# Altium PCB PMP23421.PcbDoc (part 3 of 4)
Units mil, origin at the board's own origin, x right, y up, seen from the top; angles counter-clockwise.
Board outline 2755.91 x 7559.06 mil, 8 copper layers (Top Layer, Signal Layer 1, Signal Layer 2, Signal Layer 3, Signal Layer 4, Signal Layer 5, Signal Layer 6, Bottom Layer), stack 60.4 mil thick; 211 components, 135 nets, 708 pads, 652 vias.
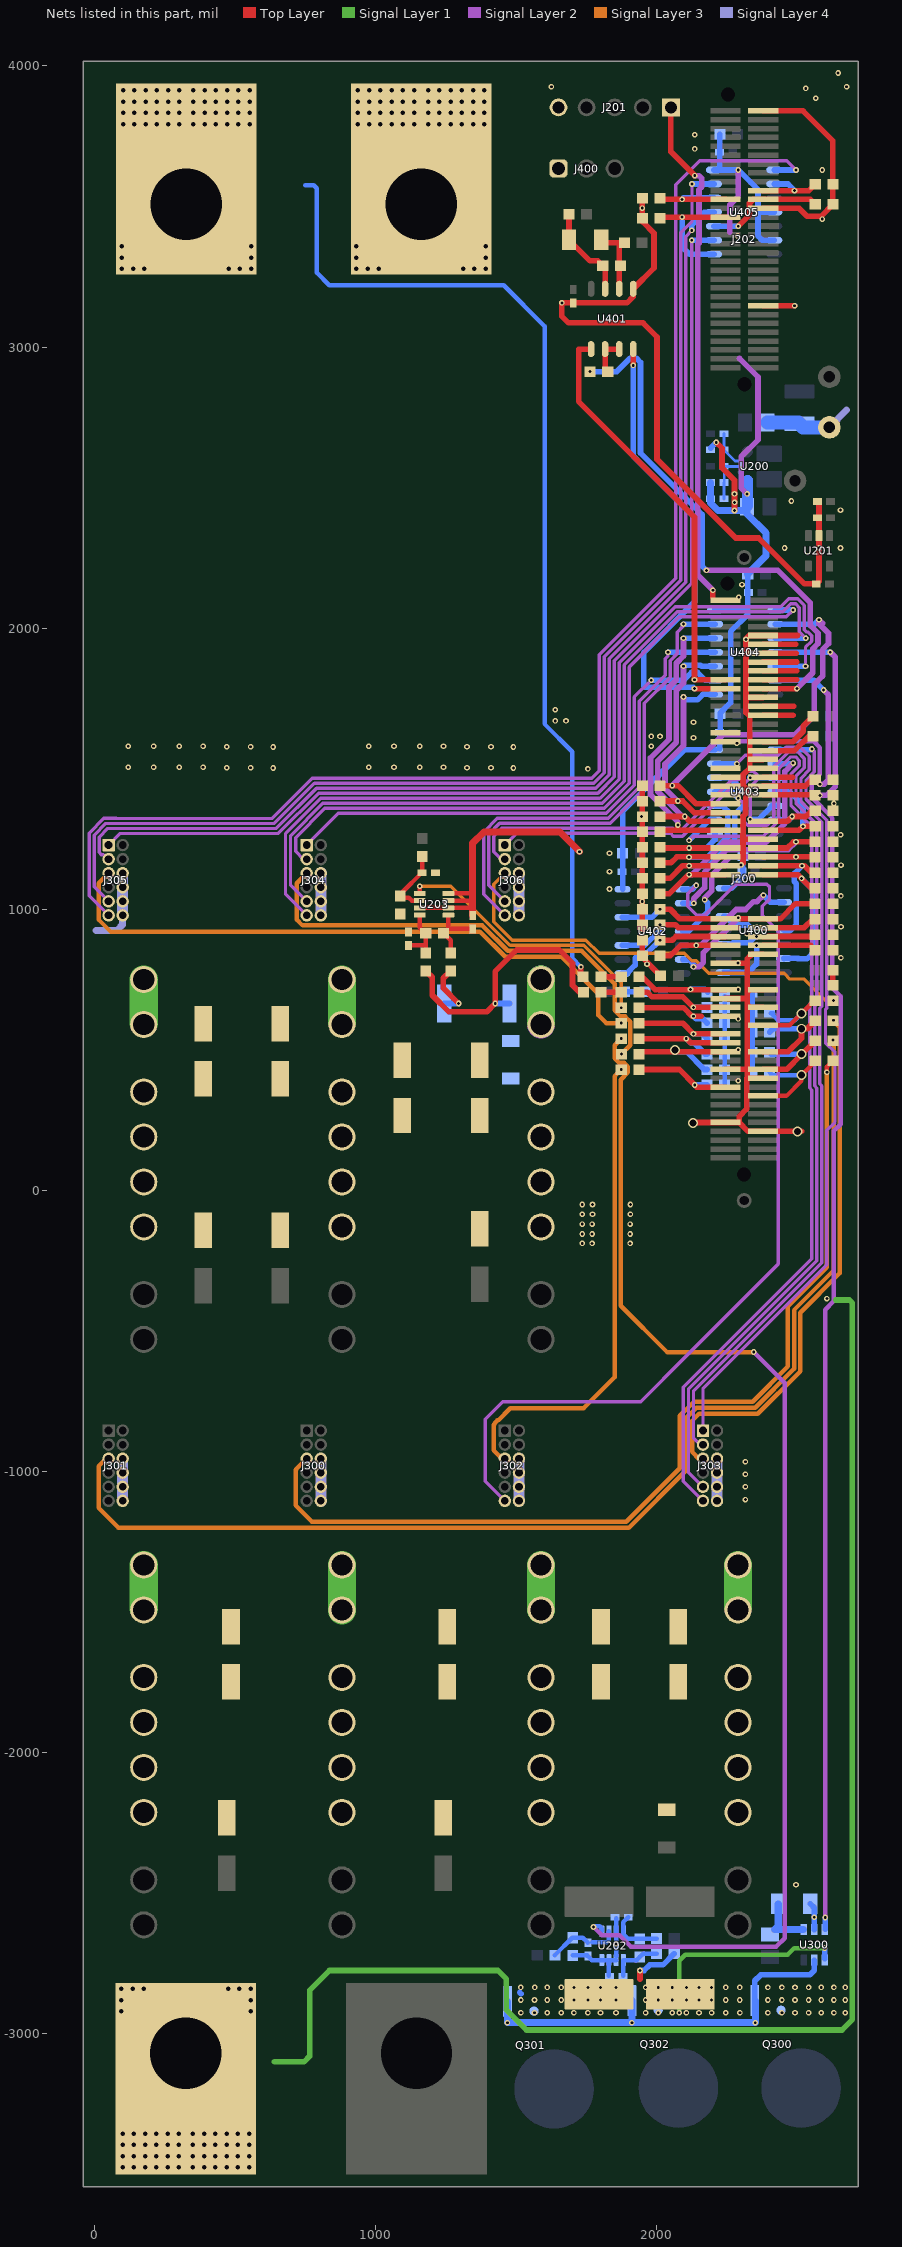
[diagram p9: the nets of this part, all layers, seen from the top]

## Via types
v1: diameter 20, hole 10, Top Layer to Bottom Layer, 398 vias
v2: diameter 32, hole 16, Top Layer to Bottom Layer, 232 vias
v3: diameter 19.68, hole 7.87, Top Layer to Bottom Layer, 12 vias
v4: diameter 35, hole 25, Top Layer to Bottom Layer, 7 vias
v5: diameter 20, hole 10, Top Layer to Bottom Layer, tented both sides, 3 vias

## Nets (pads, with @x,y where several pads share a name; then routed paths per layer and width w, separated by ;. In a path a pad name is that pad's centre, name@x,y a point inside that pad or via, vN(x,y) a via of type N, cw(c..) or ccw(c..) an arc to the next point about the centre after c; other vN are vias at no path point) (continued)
BUF_PWM6L_D: J302.11 U402.8 | length 3460.8
  Signal Layer 2 w12: J302.11@1459.45,-1104.33 1390,-1034.88 1390,-813.81 1452.21,-751.6 1942.37,-751.6 2022.94,-671.03 2022.94,-670.85 2431.97,-261.82 2431.97,921.53 2375.4,978.11 2375.4,1010.91 2400.88,1036.39 2400.88,1079.97 2391.57,1089.29 2281.12,1089.29 2170.03,978.2 2141.8,978.2 2109.61,1010.39 2109.61,1054.61 v1(2140,1085)
  Bottom Layer w20: U402.8@2092.28,1071.41 2126.41,1071.41 v1(2140,1085)
BUF_PWM7H_D: J303.1 U403.8 | length 2811.7
  Signal Layer 2 w12: J303.1@2164.17,-854.33 2164.17,-705.83 2605,-265 2605,214.2 2634,243.2 2634,491 2600,525 2600,643.28 ; v1(2551.8,1570) 2560.2,1561.6 2560.2,1488.85 2530.84,1459.49 2530.84,1390.51 2605,1316.35 2605,648.28 2600.54,643.83
  Bottom Layer w20: U403.8@2421.7,1567.72 2549.52,1567.72 v1(2551.8,1570)
BUF_PWM7L_D: J303.3 U403.6 | length 3079.9
  Signal Layer 2 w12: J303.3@2164.17,-904.33 2154.55,-904.33 2130.33,-880.1 2130.33,-714.5 2587.2,-257.63 2587.2,371.55 2579.9,378.85 2579.9,648.36 2587.2,655.66 2587.2,1308.98 2513.04,1383.14 2513.04,1466.86 2542.4,1496.22 2542.4,1543.78 2508.78,1577.4 2461.22,1577.4 2431.54,1547.72 2315,1547.72 v1(2285,1517.72)
  Bottom Layer w20: U403.6@2207.13,1517.72 v1(2285,1517.72)
BUF_PWM8H_D: J303.9 U403.4 | length 3480.8
  Signal Layer 2 w12: J303.9@2164.17,-1054.33 2112.53,-1002.68 2112.53,-707.13 2569.4,-250.25 2569.4,364.18 2562.1,371.48 2562.1,655.73 2569.4,663.03 2569.4,1301.6 2495.24,1375.77 2495.24,1474.23 2524.6,1503.6 2524.6,1536.4 2501.4,1559.6 2468.6,1559.6 2416.04,1507.04 2416.04,1322.04 2392.2,1298.2 2323.25,1298.2 2310.48,1310.97 2310.48,1374.52 v1(2290,1395)
  Bottom Layer w20: U403.4@2207.13,1417.72 2267.28,1417.72 v1(2290,1395)
BUF_PWM8L_D: J303.11 U403.2 | length 3651.2
  Signal Layer 2 w12: v1(2115,1245) 2129.91,1259.91 2379.08,1259.91 2433.84,1314.67 2433.84,1499.67 2475.97,1541.8 2494.03,1541.8 2506.8,1529.03 2506.8,1510.97 2477.44,1481.61 2477.44,1368.39 2551.6,1294.23 2551.6,670.4 2544.3,663.1 2544.3,472.86 2543.97,472.54 2543.97,364.44 2551.6,356.81 2551.6,-242.88 2094.73,-699.75 2094.73,-1034.88 J303.11@2164.17,-1104.33
  Bottom Layer w20: v1(2115,1245) 2187.72,1317.72 U403.2@2207.13,1317.72
BUF_PWM9H_C: J306.1 U403.10 | length 1083.7
  Signal Layer 2 w12: J306.1@1459.45,1228.35 1501.1,1270 2049,1270 2058.6,1260.4 2091.4,1260.4 2273.81,1442.8 2307.37,1442.8 v1(2332.28,1467.72)
  Bottom Layer w20: v1@2330,1470 v1(2332.28,1467.72) U403.10@2421.7,1467.72 U403.10@2432.8,1467.72
BUF_PWM9L_C: J306.3 U403.12 | length 1426.4
  Signal Layer 2 w12: J306.3@1459.45,1178.35 1446.65,1178.35 1420,1205 1420,1260 1447.8,1287.8 2056.37,1287.8 2065.97,1278.2 2084.03,1278.2 2266.43,1460.6 2290.6,1460.6 2320,1490 2345,1490 2355,1480 2355,1458.48 2332.28,1435.77 v1(2332.28,1320)
  Bottom Layer w20: v1(2332.28,1320) 2361.5,1320 2409.21,1367.72 U403.12@2421.7,1367.72
BUF_PWM11H_C: J306.9 U404.6 | length 1640
  Signal Layer 2 w12: J306.9@1459.45,1028.35 1402.2,1085.6 1402.2,1267.37 1440.43,1305.6 1835,1305.6 1955.8,1426.4 1955.8,1732.86 2047.4,1824.46 2047.4,1884.14 2073.2,1909.94 2073.2,1986.22 2095,2008.02 v1(2095,2014.42)
  Bottom Layer w20: v1(2095,2014.42) U404.6@2207.13,2014.42
BUF_PWM11L_C: J306.11 U404.4 | length 1637
  Signal Layer 2 w12: J306.11@1459.45,978.35 1384.4,1053.4 1384.4,1274.75 1433.05,1323.4 1827.63,1323.4 1938,1433.77 1938,1740.24 2029.6,1831.84 2029.6,1891.51 2040,1901.91 v1(2040,1914.42)
  Bottom Layer w20: v1(2040,1914.42) U404.4@2207.13,1914.42
BUF_PWM12H_D: J304.1 U404.2 | length 1903
  Signal Layer 2 w12: J304.1@754.72,1228.35 754.72,1229.73 866.2,1341.2 1820.25,1341.2 1920.2,1441.15 1920.2,1755.2 v1(1980,1815)
  Bottom Layer w20: v1(1980,1815) 2096.22,1815 2123.45,1842.23 2144.83,1842.23 2172.64,1814.42 U404.2@2207.13,1814.42
BUF_PWM12L_D: J304.3 U404.8 | length 2511
  Signal Layer 2 w12: J304.3@754.72,1178.35 742.4,1178.35 715,1205.75 715,1255 819,1359 1812.88,1359 1902.4,1448.52 1902.4,1861.82 2080.53,2039.95 2460.53,2039.95 v1(2485,2064.42)
  Bottom Layer w20: U404.8@2421.7,2064.42 v1(2485,2064.42)
BUF_PWM13H_D: J304.9 U404.10 | length 2883
  Signal Layer 2 w12: J304.9@754.72,1028.35 697.2,1085.87 697.2,1262.37 811.63,1376.8 1805.51,1376.8 1884.6,1455.89 1884.6,1869.19 2073.16,2057.75 2447.5,2057.75 2475.97,2086.22 2494.03,2086.22 2506.8,2073.45 2506.8,1987.62 v1(2530,1964.42)
  Bottom Layer w20: U404.10@2421.7,1964.42 v1(2530,1964.42)
BUF_PWM13L_D: J304.11 U404.12 | length 3112.7
  Signal Layer 2 w12: J304.11@754.72,978.35 679.4,1053.67 679.4,1269.75 804.25,1394.6 1798.13,1394.6 1866.8,1463.27 1866.8,1876.57 2065.79,2075.55 2440.13,2075.55 2468.6,2104.02 2501.4,2104.02 2524.6,2080.82 2524.6,1994.99 2533.37,1986.22 2539.03,1986.22 2551.8,1973.45 2551.8,1954.28 2528.84,1931.32 v1(2528.84,1864.42)
  Bottom Layer w20: U404.12@2421.7,1864.42 v1(2528.84,1864.42)
BUF_PWM15H_D: J305.1 U405.2 | length 4001.7
  Signal Layer 2 w12: J305.1@50,1228.35 91.4,1269.75 654.23,1269.75 796.88,1412.4 1790.76,1412.4 1849,1470.64 1849,1883.94 2124.3,2159.24 v1(2124.3,3380)
  Bottom Layer w20: v1(2124.3,3380) U405.2@2203.28,3380
BUF_PWM15L_D: J305.3 U405.4 | length 4180.4
  Signal Layer 2 w12: J305.3@50,1178.35 47.81,1178.35 31.65,1194.5 24.23,1194.5 16.15,1202.57 16.15,1256.15 47.55,1287.55 646.85,1287.55 789.51,1430.2 1783.39,1430.2 1831.2,1478.01 1831.2,1891.31 2102.5,2162.61 2102.5,3393.03 2124.3,3414.83 v1(2124.3,3415)
  Bottom Layer w20: v1(2124.3,3415) 2124.3,3435 2169.3,3480 U405.4@2203.28,3480
BUF_PWM16H_D: J305.9 U405.6 | length 4465.5
  Signal Layer 2 w12: J305.9@50,1028.35 -1.65,1079.99 -1.65,1263.53 40.17,1305.35 639.48,1305.35 782.13,1448 1776.02,1448 1813.4,1485.38 1813.4,1898.68 2084.7,2169.98 2084.7,3406.23 2125,3446.53 v1(2125,3580)
  Bottom Layer w20: v1(2125,3580) U405.6@2203.28,3580
BUF_PWM16L_D: J305.11 U405.8 | length 4978.9
  Signal Layer 2 w12: J305.11@50,978.35 -19.45,1047.79 -19.45,1270.9 33.15,1323.5 76.79,1323.5 77.14,1323.15 632.11,1323.15 774.76,1465.8 1768.64,1465.8 1795.6,1492.76 1795.6,1906.06 2066.9,2177.36 2066.9,3576.9 2152.09,3662.09 2462.91,3662.09 v1(2495,3630)
  Bottom Layer w20: U405.8@2417.84,3630 v1(2495,3630)
CAN_RX_A: J200.80
CAN_TX_A: J200.82
CS+_total_charge_current_battery: C300.1 C307.1 C308.1 R202.2 R230.2 R300.2 TP333.1 TP345.1 | length 1603.2
  Top Layer w20: R230.2@1178.11,781.04 1201.12,758.02 1201.12,694.13 1260.25,635 1395,635 v1(1425,665) 1425,778.56 1501.44,855 1653.61,855 1700.27,808.35 1700.27,729.87 1725.14,705 R202.2@1738.56,705
  Signal Layer 2 w100: TP333.1@1588.45,590 TP333.1@1588.45,590.2 TP345.1@1588.45,750.2
  Signal Layer 1 w100: TP333.1@1588.45,595 TP345.1@1588.45,750.2
  Signal Layer 3 w100: TP333.1@1588.45,593.65 TP345.1@1588.45,750.2
  Signal Layer 4 w100: TP333.1@1588.45,594.23 TP345.1@1588.45,750.2
  Bottom Layer w20: v1(1425,665) R300.2@1476.14,665
CS-_total_charge_current_battery: C301.1 C302.1 C303.1 C304.1 C305.1 C306.1 R201.2 R232.2 R300.1 T300.1 TP300.1 TP303.1 TP306.1 TP309.1 TP312.1 TP315.1 TP324.1 TP327.1 TP330.1 TP336.1 TP339.1 TP342.1 | length 4971.5
  Top Layer w20: R232.2@1266.69,781.04 1240.49,754.84 1240.49,719.51 v1(1295,665) ; R201.2@1730,763.26 v1(1730,795)
  Signal Layer 1 w100: TP309.1@175,-1487.48 TP300.1@175,-1332.48 ; TP327.1@175,595.2 TP339.1@175,750.2 ; TP312.1@879.72,-1494.72 TP312.1@879.72,-1492.48 TP303.1@879.72,-1332.48 ; TP342.1@879.72,595 TP330.1@879.72,750.2 ; TP315.1@1588.45,-1490 TP306.1@1588.45,-1332.48 ; TP336.1@2289.17,-1486.1 TP324.1@2289.17,-1332.48
  Signal Layer 3 w12: T300.1@161.42,3673.23 T300.1@326.77,3507.87
  Bottom Layer w16: 750,3575 780,3575 790,3565 790,3265 835,3220 1455,3220 1600.66,3074.34 1600.66,1659.34 1699.53,1560.47 1699.53,825.47 v1(1730,795)
  Bottom Layer w20: R300.1@1243.86,665 v1(1295,665)
  other v1: 635,1502.46 470,1503.3 555,1503.3 120,1505 210,1505 301.46,1505 386.1,1505 635,1577.46 470,1578.3 555,1578.3 120,1580 210,1580 301.46,1580 386.1,1580
  other v2: 96.77,3277.87 136.77,3277.87 176.77,3277.87 476.77,3277.87 516.77,3277.87 556.77,3277.87 96.77,3317.87 556.77,3317.87 96.77,3357.87 556.77,3357.87 101.77,3792.87 141.77,3792.87 181.77,3792.87 221.77,3792.87 261.77,3792.87 301.77,3792.87 351.77,3792.87 391.77,3792.87 431.77,3792.87 471.77,3792.87 511.77,3792.87 551.77,3792.87 101.77,3832.87 141.77,3832.87 181.77,3832.87 221.77,3832.87 261.77,3832.87 301.77,3832.87 351.77,3832.87 391.77,3832.87 431.77,3832.87 471.77,3832.87 511.77,3832.87 551.77,3832.87 101.77,3872.87 141.77,3872.87 181.77,3872.87 221.77,3872.87 261.77,3872.87 301.77,3872.87 351.77,3872.87 391.77,3872.87 431.77,3872.87 471.77,3872.87 511.77,3872.87 551.77,3872.87 101.77,3912.87 141.77,3912.87 181.77,3912.87 221.77,3912.87 261.77,3912.87 301.77,3912.87 351.77,3912.87 391.77,3912.87 431.77,3912.87 471.77,3912.87 511.77,3912.87 551.77,3912.87
CS-_total_discharge_current_bus: Q300.2-3-4-5-6-7-8 Q301.2-3-4-5-6-7-8 Q302.2-3-4-5-6-7-8 R228.2 R301.2 R302.2 U300.4 | length 942.5
  Top Layer w20: 1940,-2805 v1(1940,-2775)
  Signal Layer 1 w16: v1(2080,-2925) 2080,-2740 2100.94,-2719.06 2465.18,-2719.06 2489.24,-2695 v1(2597.4,-2695)
  Bottom Layer w20: 1511.81,-2853.35 1516.73,-2858.27 ; v1(1940,-2775) 1955,-2775 1975,-2755 2022.1,-2755 R228.2@2062.1,-2715 ; U300.4@2597.4,-2732.5 v1(2597.4,-2695)
  other v1: 1516.54,-2925 1565,-2925 1610,-2925 1660,-2925 1705,-2925 1755,-2925 1799.53,-2925 1854.88,-2925 1960,-2925 2005,-2925 2055,-2925 2105.27,-2925 2150.27,-2925 2195,-2925 2245,-2925 2295.56,-2925 2395.12,-2925 2445,-2925 2491.77,-2925 2540,-2925 2585,-2925 2630,-2925 2670,-2925 1516.54,-2880 1565,-2880 1610,-2880 1660,-2880 1705,-2880 1755,-2880 1799.53,-2880 1854.88,-2880 1960,-2880 2005,-2880 2055,-2880 2105.27,-2880 2150.27,-2880 2195,-2880 2245,-2880 2295,-2880 2395.12,-2880 2445,-2880 2491.77,-2880 2540,-2880 2585,-2880 2630,-2880 2670,-2880 1516.07,-2835 1566.07,-2835 1610,-2835 1660,-2835 1705,-2835 1755,-2835 1799.53,-2835 1855,-2835 1960,-2835 2005,-2835 2055,-2835 2105.27,-2835 2150,-2835 2195,-2835 2245,-2835 2295,-2835 2395.12,-2835 2445,-2835 2491.77,-2835 2540,-2835 2585,-2835 2630,-2835 2670,-2835
Fan: J200.79 | length 105.5
  Top Layer w20: J200.79@2377.73,1469.98 2483.21,1469.98
I2C_A_SCL: J200.87 R224.1 | length 227.8
  Top Layer w20: J200.87@2377.73,1595.96 2484.48,1595.96 2520.86,1632.35 2520.86,1651.71 R224.1@2556.34,1687.2
I2C_A_SDA: J200.85 R223.1 | length 199.8
  Top Layer w20: J200.85@2377.73,1564.47 2489.47,1564.47 2540.72,1615.72 R223.1@2556.34,1615.72
ICS_1ph: J300.5 R200.1 | length 3448.1
  Top Layer w16: v1@2605,420 2605,439.01 R200.1@2626.5,460.51
  Signal Layer 3 w16: J300.5@754.72,-954.33 754.03,-954.33 718.88,-989.48 718.88,-990.18 715.75,-993.31 715.75,-1120.75 773.2,-1178.2 1891.8,-1178.2 2081.6,-988.4 2081.6,-801.94 2132.14,-751.4 2340.84,-751.4 2466.4,-625.84 2466.4,-412.61 2605,-274.01 v1@2605,420
  other v1: 2605,420.14
ICS_2ph: J301.5 R205.1 | length 4268
  Signal Layer 3 w16: J301.5@50,-954.33 40.67,-954.33 14.15,-980.85 14.15,-1129.15 85,-1200 1900.83,-1200 2103.4,-997.43 2103.4,-810.97 2141.17,-773.2 2349.87,-773.2 2488.2,-634.87 2488.2,-425.64 2628.8,-285.04 2628.8,529.74 v1@2626.5,532.05
  other v1: 2626.5,535
ICS_3ph: J302.5 R206.2 | length 1748
  Signal Layer 3 w16: J302.5@1459.45,-954.33 1449.8,-954.33 1420.47,-925 1420.47,-833.69 1423.6,-830.56 1423.6,-827.73 1432.85,-818.48 1435.68,-818.48 1479.16,-775 1739.53,-775 1849.53,-665 1849.53,406.03 v1(1873.5,430)
ICS_4ph: J303.5 R213.1 | length 1932.6
  Signal Layer 3 w16: J303.5@2164.17,-954.33 2149.33,-954.33 2125.2,-930.2 2125.2,-820 2150.2,-795 2358.9,-795 2510,-643.9 2510,-434.67 2650.6,-294.07 2650.6,579.42 v1@2626.5,603.52
  other v1: 2628.8,605
ICS_5ph: J304.5 R207.2 | length 1700.7
  Signal Layer 3 w16: J304.5@754.72,1128.35 754.03,1128.35 718.88,1093.19 718.88,963.5 739.88,942.5 1379.33,942.5 1469.43,852.4 1732.43,852.4 1849.7,735.12 1849.7,640.14 1871.05,618.8 1886.94,618.8 1905,600.74 1905,515.98 v1(1874.02,485)
ICS_6ph: J305.5 R212.2 | length 2238.2
  Signal Layer 3 w16: J305.5@50,1128.35 49.3,1128.35 14.15,1093.2 14.15,963.5 56.95,920.7 1370.3,920.7 1460.4,830.6 1660.74,830.6 1792.27,699.08 1792.27,623.76 1821.02,595 v1(1873.43,595) ; v1@1873.54,595.11 v1@1875,593.65
ICS_7ph: J306.5 R218.1 | length 1515.7
  Signal Layer 3 w12: J306.5@1459.45,1128.35 1420,1088.9 1420,955 1485,890 1748,890 1794.79,843.21 2097.89,843.21 2124.3,816.8 2139.7,816.8 2184.34,772.16 2452.54,772.16 2472.9,751.8 2524.03,751.8 2600.83,675 v1@2630,675
  other v1: 2628.8,675
MCU_RESET: J200.120 J201.1 | length 1824.5
  Top Layer w20: J201.1@2050.27,3852.41 2050.27,3694.73 v1(2135,3610) ; 2199.53,2110 v1(2199.53,2135)
  Signal Layer 2 w20: v1(2135,3610) 2150,3610 2160,3600 2160,3570 2150.1,3560.1 2150.1,3369.31 2146.1,3365.31 2146.1,2188.43 v1(2199.53,2135)
NetC200_1: C200.1 J200.15 R200.2 | length 367.4
  Top Layer w16: J200.15@2377.73,336.12 2461.12,336.12 2514.67,389.67 v4(2514.67,410) 2563.5,458.83 R200.2@2563.5,460.51
  Bottom Layer w16: C200.1@2401.5,419.75 2411.25,410 v4(2514.67,410)
NetC201_1: C201.1 J200.21 R205.2 | length 335.9
  Top Layer w20: J200.21@2377.73,430.61 2462.04,430.61 2515,483.57 v4(2515,485) 2516.46,485 R205.2@2563.5,532.05
  Bottom Layer w20: C201.1@2407.72,485 v4(2515,485)
NetC202_1: C202.1 J200.18 R206.1 | length 376.6
  Top Layer w20: R206.1@1936.5,430 2080.14,430 v1(2135,375.14) 2142.52,367.62 J200.18@2243.87,367.62
  Bottom Layer w20: v1(2135,375.14) C202.1@2178.37,375.14
NetC203_1: C203.1 J200.26 R207.1 | length 441.1
  Top Layer w20: R207.1@1945.61,493.6 J200.26@2243.87,493.6
  Bottom Layer w20: v4(2064.67,500) 2071.07,493.6 2105,493.6 2168.6,430 C203.1@2178.5,430
NetC204_1: C204.1 J200.30 R212.1 | length 372.6
  Top Layer w20: R212.1@1936.42,595 2092.26,595 v1(2130.67,556.59) ; v1@2136.12,556.59 J200.30@2243.87,556.59
  Bottom Layer w20: v1(2130.67,556.59) 2161.91,556.59 C204.1@2178.5,540
NetC205_1: C205.1 J200.25 R213.2 | length 369.7
  Top Layer w20: J200.25@2377.73,493.6 2467.6,493.6 2514.67,540.68 v4(2514.67,575) 2534.98,575 R213.2@2563.5,603.52
  Bottom Layer w20: C205.1@2401.5,562.7 2413.79,575 v4(2514.67,575)
NetC206_1: C206.1 J200.31 R218.2 | length 347.6
  Top Layer w16: J200.31@2377.73,588.09 2473.09,588.09 2560,675 R218.2@2563.5,675
  Bottom Layer w16: C206.1@2406.17,629.51 C206.1@2415,629.51 ; C206.1@2415,622.33 2432.33,605 2490.17,605 v4(2514.67,629.51)
NetC211_1: C211.1 R219.1 R222.2 U200.6 | length 173.9
  Bottom Layer w10: R222.2@2238.69,2460 C211.1@2238.69,2518.01 2239.73,2519.05 2239.73,2574.97 U200.6@2298.23,2574.97
NetC214_1: C214.1 C215.1 R226.1 U202.8 | length 191.9
  Bottom Layer w16: C215.1@1898.62,-2585.06 1881.09,-2602.59 U202.8@1881.09,-2635.24 1881.09,-2645.02 1897.19,-2661.13 R226.1@1999.1,-2661.13
NetC214_2: C214.2 C216.1 R228.1 U202.1 | length 182.8
  Bottom Layer w16: C216.1@1881.09,-2793.03 U202.1@1881.09,-2737.6 1928.9,-2737.6 C214.2@1940,-2726.5 1951.5,-2715 R228.1@1999.1,-2715
NetC217_1: C217.1 C218.1 R225.2 U202.6 | length 244.9
  Bottom Layer w16: R225.2@1637.7,-2720 1699.2,-2658.5 C217.1@1700.27,-2658.5 1737.13,-2658.5 C218.1@1755,-2676.38 ; 1770,-2675 1821.44,-2675 1829.91,-2666.54 U202.6@1829.91,-2635.24
NetC220_1: C220.1 C221.1 R230.1 U203.8 | length 203.3
  Top Layer w16: C221.1@1116.93,871.38 1176.7,871.38 ; U203.8@1156.46,979.41 1156.46,934.49 C220.1@1176.08,914.87 ; R230.1@1178.11,844.03 C220.1@1178.11,914.87
NetC220_2: C220.2 C222.1 R232.1 U203.1 | length 240.8
  Top Layer w16: U203.1@1258.82,979.41 C220.2@1258.82,933.15 ; R232.1@1266.69,844.03 1266.69,889.84 C220.2@1241.1,915.43 C220.2@1258.82,933.15 ; C222.1@1344.99,930.02 1261.95,930.02 C220.2@1258.82,933.15
NetC223_1: C223.1 C224.1 R229.2 U203.6 | length 232.2
  Top Layer w16: C223.1@1095,1041.42 1118.05,1041.42 1128.88,1030.59 U203.6@1156.46,1030.59 ; C223.1@1095,1051.2 1095,1060.61 1165,1130.61 R229.2@1165,1188.5
NetC314_1: C314.1 R303.1 U300.1 | length 199.8
  Bottom Layer w25: C314.1@2432.05,-2537.98 2432.05,-2617.17 2419.58,-2629.64 U300.1@2522.6,-2629.64
NetC401_1: C401.1 R404.1 R408.2 U401.7 | length 335.6
  Top Layer w20: R404.1@1687.63,3473.09 C401.1@1687.63,3381.25 1762.19,3306.69 1790.42,3306.69 R408.2@1807.71,3289.4 1816.18,3280.93 U401.7@1816.18,3207.28
NetC401_2: C401.2 R408.1 R411.1 U401.6 | length 218.4
  Top Layer w20: C401.2@1811.39,3371.66 1864.8,3371.66 1866.18,3370.29 U401.6@1866.18,3207.28
NetQ300_1: Q300.1 Q301.1 Q302.1 U300.5 | length 1446.1
  Bottom Layer w20: Q300.1@2348.43,-2881.89 2348.43,-2811.57 2370,-2790 2545,-2790 2560,-2775 U300.5@2560,-2737.9
  Bottom Layer w25: Q301.1@1468.5,-2886.02 v5(1468.5,-2960.63) v5(1911.42,-2960.63) ; Q302.1@1911.42,-2881.89 v5(1911.42,-2960.63) ; Q300.1@2350.39,-2883.86 v5(2350.39,-2960.63) v5(1911.42,-2960.63)
NetR201_1: R201.1 R208.2 | length 74
  Top Layer w20: R201.1@1800.83,760.67 R208.2@1874.81,760.67
NetR202_1: R202.1 R209.2 | length 74
  Top Layer w20: R202.1@1801.55,705 R209.2@1875.53,705
NetR203_1: R203.1 R210.2 | length 74
  Bottom Layer w20: R203.1@1884.79,707.06 R210.2@1958.77,707.06
NetR204_1: R204.1 R211.2 | length 53.5
  Top Layer w20: R211.2@2626.5,730 R204.1@2626.5,783.52
NetR220_1: R220.1 R221.2 U200.7 | length 133.9
  Bottom Layer w10: R220.1@2238.69,2692.04 R221.2@2238.69,2634.03 2278.06,2594.66 U200.7@2298.23,2594.66
NetR227_1: R227.1 U202.5 | length 4436.9
  Signal Layer 2 w16: v1(1775,-2620) 1805,-2650 1867.4,-2650 1907.07,-2689.67 2425.33,-2689.67 2455,-2660 2455,-685 v1(2345,-575)
  Signal Layer 3 w16: v1(1873.5,540) 1850.22,516.71 1850.22,469.27 1865.69,453.8 1883.36,453.8 1897.3,439.86 1897.3,420.14 1871.33,394.17 1871.33,-410 2036.33,-575 v1(2345,-575)
  Bottom Layer w16: v1@1776.57,-2620 1779.41,-2617.17 1797.41,-2617.17 1804.31,-2624.08 U202.5@1804.31,-2635.24
NetR231_1: R231.1 U203.5 | length 975.5
  Top Layer w16: U203.5@1156.46,1056.18 v1(1156.46,1082.2)
  Signal Layer 3 w12: v1(1156.46,1082.2) 1267.63,1082.2 1477.63,872.2 1740.63,872.2 1874.02,738.81 v1@1874.02,649.12
  other v1: 1873.5,650
NetR407_2: R407.2 U401.2 U401.3 | length 120.9
  Top Layer w20: R407.2@1816.18,2921.82 U401.2@1816.18,2992.72 U401.3@1866.18,2992.72
ORING_CONTROL: J200.88 U300.3 | length 4630.4
  Top Layer w16: J200.88@2243.87,1595.96 2279.98,1595.96 v1(2285,1590.94)
  Signal Layer 2 w16: v1(2285,1590.94) 2291.26,1597.2 2558.26,1597.2 2580,1575.46 2580,1480.65 2550.64,1451.29 2550.64,1398.71 2624.8,1324.55 2624.8,719 2653.8,690 2653.8,235 2628.8,210 2628.8,-394.86 2599.37,-424.29 v1(2599.37,-2586.3)
  Bottom Layer w20: U300.3@2599.37,-2627.67 v1(2599.37,-2586.3)
PSKILL: J200.101 | length 120.6
  Top Layer w20: J200.101@2377.73,1816.43 2498.31,1816.43
PWM1H_D: J200.49 R400.2 U400.1 | length 392.8
  Top Layer w20: J200.49@2377.73,871.55 2546.85,871.55 R400.2@2563.4,855
  Bottom Layer w20: U400.1@2237.72,775 2325.16,775 2355.23,805.07 v1@2355.23,871.41 ; v1@2355,867.45 v1(2355,871.41)
PWM1L_D: J200.51 R402.2 U400.3 | length 307.6
  Top Layer w20: J200.51@2377.73,903.05 R402.2@2556.45,903.05
  Bottom Layer w20: U400.3@2237.72,875 2265.69,875 2271.49,880.8 2327.9,880.8 2350.1,903 v1(2355,903)
PWM2H_D: J200.53 R405.2 U400.5 | length 332.4
  Top Layer w20: J200.53@2377.73,934.54 2524.54,934.54 2555,965 R405.2@2563.4,965
  Bottom Layer w20: U400.5@2237.72,975 2243.96,975 2274.76,944.2 2323.99,944.2 2333.33,934.85 v1@2355.15,934.85
  other v1: 2355,935
PWM2L_D: J200.55 R401.2 U402.13 | length 604.7
  Top Layer w20: v1(2290,970) 2293.96,966.04 J200.55@2377.73,966.04 2440.04,966.04 2494,1020 R401.2@2563.4,1020
  Signal Layer 2 w20: v1(2130.67,795) 2149.73,795 2165.8,811.07 2165.8,845.8 v1(2290,970)
  Bottom Layer w20: U402.13@2092.28,821.41 2114.26,821.41 2130.67,805 v1(2130.67,795)
PWM3H_D: J200.50 R409.2 U400.9 | length 644.1
  Top Layer w20: R409.2@2011.5,835 2048.05,835 2084.6,871.55 v1(2140,871.55) J200.50@2243.87,871.55
  Signal Layer 2 w20: v1(2140,871.55) 2155.07,871.55 2282.71,999.2 2315.8,999.2 2343.89,1027.29 2356.37,1027.29 v1(2379.08,1050)
  Bottom Layer w20: v1(2379.08,1050) 2404.08,1025 U400.9@2452.28,1025
PWM3L_D: J200.52 R415.2 U402.1 | length 435.2
  Top Layer w20: v1(2011.5,890) 2055,890 2068.05,903.05 J200.52@2243.87,903.05
  Bottom Layer w20: U402.1@1877.72,771.41 1892.91,771.41 1922.66,801.16 1922.66,826.03 1942.24,845.61 1948.59,845.61 1948.74,845.75 1967.25,845.75 v1(2011.5,890)
PWM4H_D: J200.54 R413.2 U402.3 | length 416
  Top Layer w20: v1(2011.5,945) 2066.25,945 2076.7,934.54 J200.54@2243.87,934.54
  Bottom Layer w20: U402.3@1877.72,871.41 1937.91,871.41 1938.05,871.55 ; 1933.81,871.55 1938.05,871.55 ; v1(2011.5,945) 2011.5,926.49 1956.56,871.55 1938.05,871.55
PWM4L_D: J200.56 R406.2 U402.5 | length 392.1
  Top Layer w20: v1(2011.5,1000) 2047.73,1000 2081.69,966.04 J200.56@2243.87,966.04
  Bottom Layer w20: U402.5@1877.72,971.41 1982.91,971.41 v1(2011.5,1000)
PWM5H_D: J200.57 R412.2 U400.13 | length 607.7
  Top Layer w20: J200.57@2377.73,1123.52 2501.22,1123.52 v1(2515,1109.74) 2550.96,1073.78 2562.18,1073.78 R412.2@2563.4,1075
  Bottom Layer w20: U400.13@2452.28,825 2452.28,825.8 2500.85,825.8 2501.65,825 2503.51,825 2504.7,823.81 2533.81,823.81 2562.79,852.79 2562.79,1061.94 v1(2515,1109.74)
PWM5L_D: J200.59 R414.2 U400.11 | length 472.3
  Top Layer w20: J200.59@2377.73,1155.02 2524.98,1155.02 2550,1130 R414.2@2563.4,1130
  Bottom Layer w20: U400.11@2452.28,925 2475.46,925 2496.63,946.17 2496.63,1091.62 2489.2,1099.05 2489.2,1127.77 v1(2516.43,1155)
PWM6H_D: J200.61 R403.2 U402.11 | length 776.6
  Top Layer w20: J200.61@2377.73,1186.51 v1(2495,1186.51) 2561.89,1186.51 R403.2@2563.4,1185
  Signal Layer 2 w20: v1(2170,1034.17) 2170,1040.51 2195.8,1066.31 2195.8,1121.79 2260.52,1186.51 v1(2495,1186.51)
  Bottom Layer w20: U402.11@2092.28,921.41 2112.9,921.41 2180.8,989.31 2180.8,1023.37 v1(2170,1034.17)
PWM6L_D: J200.63 R410.2 U402.9 | length 730.5
  Top Layer w20: J200.63@2377.73,1218.01 2463.61,1218.01 2485.6,1240 v1(2495,1240) R410.2@2563.4,1240
  Signal Layer 2 w20: v1(2131.41,1021.41) 2131.41,1038.4 2170,1076.99 2170,1132.48 2249.84,1212.31 2467.31,1212.31 v1(2495,1240)
  Bottom Layer w20: U402.9@2092.28,1021.41 v1(2131.41,1021.41)
PWM7H_D: J200.58 R416.2 U403.9 | length 967.6
  Top Layer w20: R416.2@2011.5,1055 2044.01,1055 2112.53,1123.52 v1(2115,1123.52) J200.58@2243.87,1123.52
  Signal Layer 2 w20: v1(2115,1123.52) 2124.56,1123.52 2239.15,1238.11 2388.11,1238.11 2455.64,1305.64 2455.64,1490.64 v1(2485,1520)
  Bottom Layer w20: U403.9@2421.7,1517.72 2482.72,1517.72 v1(2485,1520)
PWM7L_D: J200.60 R419.2 U403.5 | length 764.5
  Top Layer w20: R419.2@2011.5,1110 2046.27,1110 2091.29,1155.02 v1(2115,1155.02) J200.60@2243.87,1155.02
  Bottom Layer w20: v1(2115,1155.02) 2186.7,1155.02 2277.55,1245.86 2277.55,1338.23 2315.8,1376.49 2315.8,1411.23 2259.31,1467.72 U403.5@2207.13,1467.72
PWM8H_D: J200.62 R422.2 U403.3 | length 553.6
  Top Layer w20: R422.2@2011.5,1165 2049.76,1165 2071.27,1186.51 J200.62@2243.87,1186.51
  Bottom Layer w20: v1(2114.46,1185) 2180.2,1185 2251.47,1256.28 2251.47,1289.73 2251.75,1290 2251.75,1350 2234.03,1367.72 U403.3@2207.13,1367.72
PWM8L_D: J200.64 R425.2 U403.1 | length 354.4
  Top Layer w20: R425.2@2013.49,1218.01 v1(2115,1218.01) J200.64@2243.87,1218.01
  Bottom Layer w20: v1(2115,1218.01) 2176.72,1218.01 2207.13,1248.42 U403.1@2207.13,1267.72
PWM9H_C: J200.67 R428.2 U403.11 | length 384.8
  Top Layer w20: J200.67@2377.73,1281 2506,1281 v1(2520,1295) R428.2@2563.4,1295
  Bottom Layer w20: U403.11@2421.7,1417.72 2466.87,1417.72 2474.58,1410 2480.5,1410 2520,1370.5 v1(2520,1295)
PWM9L_C: J200.69 R430.2 U403.13 | length 266
  Top Layer w20: J200.69@2377.73,1312.5 2463.94,1312.5 v1(2481.44,1330) 2530.17,1330 2550.17,1350 R430.2@2563.4,1350
  Bottom Layer w20: U403.13@2421.7,1317.72 2469.15,1317.72 v1(2481.44,1330)
PWM11H_C: J200.68 R423.2 U404.5 | length 1110.9
  Top Layer w20: R423.2@2017.5,1281 2075,1281 ; v1(2075,1300) 2075,1281 ; J200.68@2243.87,1281 2075,1281
  Signal Layer 2 w20: v1(2075,1300) 2075,1310.54 1977.6,1407.94 1977.6,1538.39 2043.4,1604.19 2043.4,1789.63 2069.2,1815.43 2069.2,1875.11 2095,1900.91 v1(2095,1964.42)
  Bottom Layer w20: v1(2095,1964.42) U404.5@2207.13,1964.42
PWM11L_C: J200.70 R420.2 U404.3 | length 971.4
  Top Layer w20: R420.2@2011.5,1330 v1(2099.65,1330) 2117.16,1312.5 J200.70@2243.87,1312.5
  Signal Layer 2 w20: v1(2095,1864.42) 2095,1804.75 2069.2,1778.95 2069.2,1593.51 2003.4,1527.71 2003.4,1418.63 2092.03,1330 v1(2099.65,1330)
  Bottom Layer w20: v1(2095,1864.42) 2098.62,1868.03 2155.51,1868.03 2159.13,1864.42 U404.3@2207.13,1864.42
PWM12H_D: J200.72 R417.2 U404.1 | length 789.3
  Top Layer w20: R417.2@2011.5,1385 v1(2075,1385) 2091.71,1385 2132.71,1343.99 J200.72@2243.87,1343.99
  Signal Layer 2 w20: v1@2073.51,1385 2029.2,1429.31 2029.2,1517.02 2095,1582.82 v1(2095,1755)
  Bottom Layer w20: v1(2095,1755) 2105,1745 2144.75,1745 2164.17,1764.42 U404.1@2207.13,1764.42
PWM12L_D: J200.74 R426.2 U404.9 | length 1423
  Top Layer w20: R426.2@2011.5,1440 v1(2055,1440) 2074.89,1440 2139.4,1375.49 J200.74@2243.87,1375.49
  Signal Layer 2 w20: v1(2055,1440) 2236,1621 2491,1621 2560,1690 2560,1800 2590,1830 2590,1924 2610.8,1944.8 2610.8,1981.77 2576.82,2015.74 v1(2576.82,2030) 2590,2016.82
  Bottom Layer w20: U404.9@2421.7,2014.42 2561.24,2014.42 v1(2576.82,2030)
PWM13H_D: J200.75 R429.2 U404.11 | length 935.3
  Top Layer w20: J200.75@2377.73,1406.99 2561.42,1406.99 R429.2@2563.4,1405
  Signal Layer 2 w20: v1(2580,1405) 2603.78,1405 2635,1436.22 2635,1896.32 v1(2616.91,1914.42)
  Bottom Layer w20: U404.11@2421.7,1914.42 v1(2616.91,1914.42)
PWM13L_D: J200.77 R431.2 U404.13 | length 743.1
  Top Layer w20: J200.77@2377.73,1438.48 2528.31,1438.48 2549.83,1460 R431.2@2563.5,1460
  Signal Layer 2 w20: v1(2580,1445) 2595,1445 2609.2,1459.2 2609.2,1764.2 v1(2593.4,1780)
  Bottom Layer w20: U404.13@2421.7,1814.42 2558.98,1814.42 v1(2593.4,1780)
PWM15H_D: J202.156 R418.2 U405.1 | length 459.5
  Top Layer w20: R418.2@2015.08,3462.1 v1(2090,3462.1) J202.156@2244.73,3462.1
  Bottom Layer w20: v1(2090,3462.1) 2090,3356.54 2116.54,3330 U405.1@2203.28,3330
PWM15L_D: J202.159 R421.2 U405.3 | length 431.4
  Top Layer w20: v1(2290,3430) 2329.67,3469.67 2329.67,3511.71 2343.06,3525.1 J202.159@2378.59,3525.1 2546.28,3525.1 R421.2@2563.5,3507.87
  Bottom Layer w20: U405.3@2203.28,3430 v1(2290,3430)
PWM16H_D: J202.160 R424.2 U405.5 | length 343.6
  Top Layer w20: R424.2@2016.4,3525.1 v1(2090,3525.1) J202.160@2244.73,3525.1
  Bottom Layer w20: v1(2090,3525.1) 2094.9,3530 U405.5@2203.28,3530
PWM16L_D: J202.161 R427.2 U405.9 | length 276.2
  Top Layer w20: J202.161@2378.59,3556.59 v1(2490,3556.59) 2540.75,3556.59 R427.2@2563.5,3579.35
  Bottom Layer w20: U405.9@2417.84,3580 2466.59,3580 v1(2490,3556.59)
RACK_ADD_0: J200.105 | length 120.6
  Top Layer w20: J200.105@2377.73,1879.43 2498.31,1879.43
RACK_ADD_1: J200.107 | length 118.6
  Top Layer w20: J200.107@2377.73,1910.92 2496.35,1910.92
RACK_ADD_2: J200.109 | length 116
  Top Layer w20: J200.109@2377.73,1942.42 2493.74,1942.42
RS485_Control: J200.99 R407.1 | length 1929.3
  Top Layer w20: J200.99@2377.73,1784.94 v1(2498.31,1784.94)
  Signal Layer 2 w20: v1(2176.72,2205.58) 2430.67,2205.58 2546.4,2089.85 2546.4,2009.68 2573.6,1982.48 2573.6,1945.25 2554.64,1926.29 2554.64,1841.26 v1(2498.31,1784.94)
  Bottom Layer w20: v1(1762.44,2912.57) 1857.42,2912.57 1905.49,2960.64 1926.86,2960.64 1941.98,2945.53 1941.98,2623.02 2160.8,2404.2 2160.8,2220 2162.3,2220 v1(2176.72,2205.58)
SCI_B_RX_RS485-: J200.102 U401.1 | length 1500.8
  Top Layer w20: U401.1@1766.18,2992.72 1722.08,2992.72 1722.08,2806.43 2134.14,2394.37 v1(2134.14,1816.43) J200.102@2243.87,1816.43
SCI_B_TX_RS485+: J200.100 U401.4 | length 1656.6
  Top Layer w20: v1(1916.18,2934.84) U401.4@1916.18,2992.72 ; v1(2134.14,1784.94) J200.100@2243.87,1784.94
  Bottom Layer w20: v1(1916.18,2934.84) 1916.18,2612.34 2135,2393.51 2135,2094.42 1954.2,1913.62 1954.2,1795.8 1960.8,1789.2 2129.88,1789.2 v1(2134.14,1784.94)
SGND: C200.2 C201.2 C202.2 C203.2 C204.2 C205.2 C206.2 C207.2 C208.2 C209.2 C210.2 C211.2 C212.2 C213.2 C215.2 C216.2 C217.2 C218.2 C219.2 C221.2 C222.2 C223.2 C224.2 C225.2 C309.2 C310.2 C311.2 C312.2 C313.2 C314.2 C315.2 C400.1 C402.2 C403.1 C404.2 C405.1 C406.2 C407.1 C408.2 C409.1 C410.2 C411.1 J200.7 J200.10 J200.19 J200.22 J200.35 J200.38 J200.39 J200.46 J200.47 J200.65 J200.83 J200.97 J200.111 J201.5 J202.135 J202.157 J202.179 J300.6 J300.8 J300.10 J300.12 J301.6 J301.8 J301.10 J301.12 J302.6 J302.8 J302.10 J302.12 J303.6 J303.8 J303.10 J303.12 J304.6 J304.8 J304.10 J304.12 J305.6 J305.8 J305.10 J305.12 J306.6 J306.8 J306.10 J306.12 J400.1 R214.1 R215.1 R216.1 R217.1 R221.1 R222.1 R400.1 R401.1 R402.1 R403.1 R405.1 R406.1 R409.1 R410.1 R412.1 R413.1 R414.1 R415.1 R416.1 R417.1 R418.1 R419.1 R420.1 R421.1 R422.1 R423.1 R424.1 R425.1 R426.1 R427.1 R428.1 R429.1 R430.1 R431.1 SGND.1 T303.1 TP314.1 TP317.1 TP318.1 TP321.1 TP322.1 TP323.1 TP335.1 TP348.1 TP349.1 TP350.1 TP351.1 TP352.1 TP353.1 TP354.1 U200.4 U201.2 U202.2 U202.3 U202.4 U202.7 U203.2 U203.3 U203.4 U203.7 U300.2 U400.7 U401.5 U402.7 U403.7 U404.7 U405.7 U405.11 U405.13 | length 19420.5
  Top Layer w16: U203.7@1156.46,1005 U203.2@1258.82,1005 1342.43,1005 ; U203.3@1258.82,1030.59 1341.65,1030.59 1344.99,1027.24 ; U203.4@1258.82,1056.18 1340.47,1056.18 1341.65,1055
  Top Layer w20: R426.1@1948.5,1440 R417.1@1948.5,1385 R420.1@1948.5,1330 R423.1@1948.5,1275 R425.1@1948.5,1220 R422.1@1948.5,1165 R419.1@1948.5,1110 R416.1@1948.5,1055 R406.1@1948.5,1000 R413.1@1948.5,945 R415.1@1948.5,890 R409.1@1948.5,835 1948.5,828.52 R216.1@2013.5,763.52 ; R424.1@1948.5,3530 R418.1@1948.5,3458.52 1948.5,3446.5 1990,3405 1990,3281.11 U401.5@1916.18,3207.28 1916.18,3179.2 1894.06,3157.09 C400.1@1703.38,3157.09 v1(1662.44,3157.09) 1662.44,3109.05 1685.69,3085.8 1950.69,3085.8 2000.8,3035.69 2000.8,2600.69 2280.69,2320.8 2362.08,2320.8 2525.55,2157.33 C212.2@2567.26,2157.33 2576.82,2166.89 v1(2576.82,2285) U201.2@2576.82,2329.13 C213.2@2576.82,2445.05 ; v4@2129.87,241.63 J200.10@2243.87,241.63 J200.10@2293.38,241.63 ; v1(2211.55,2660.71) 2231.8,2640.47 2231.8,2570.79 2276.51,2526.07 v1(2276.51,2418.58) ; J200.22@2243.87,430.61 2319.72,430.61 2321.15,429.18 ; J200.38@2243.87,682.58 2320.61,682.58 ; J200.46@2243.87,808.56 2319.71,808.56 ; v1(2300,1158.08) 2306.48,1164.57 2306.48,1330.69 2315.8,1340 2315.8,1432.6 2306.48,1441.92 2306.48,1478.4 2330.99,1502.91 J200.83@2330.99,1532.97 ; 2308.55,1249.51 J200.65@2377.73,1249.51 ; 2322.58,1753.44 J200.97@2377.73,1753.44 ; J200.19@2377.73,399.11 2319.72,399.11 ; J200.35@2377.73,651.08 2332.53,651.08 2321.15,662.47 ; J200.39@2377.73,714.07 2332.42,714.07 2321.15,702.8 ; J200.47@2377.73,840.06 2337.59,840.06 2321.15,823.61 2321.15,702.8 ; J200.83@2377.73,1532.97 J200.83@2330.99,1532.97 ; J202.135@2378.59,3147.14 v1(2490.03,3147.14) ; J202.157@2378.59,3493.6 2506.4,3493.6 2535,3465 2583.62,3465 R421.1@2626.5,3507.87 R427.1@2626.5,3579.35 2626.5,3733.5 2519.94,3840.06 J202.179@2378.59,3840.06 ; 2500.43,1973.91 J200.111@2377.73,1973.91 2328.48,1973.91 2317.21,1962.64 2317.21,1699.36 2330.99,1685.59 J200.83@2330.99,1532.97 ; v4@2514.67,210 2514.54,210.14 J200.7@2377.73,210.14 2324.88,210.14 J200.10@2293.38,241.63 ; J200.10@2293.38,241.63 2293.38,263.44 2319.72,289.77 2319.72,399.11 ; 2319.72,399.11 2321.15,400.54 2321.15,429.18 ; 2321.15,429.18 2321.15,662.47 ; 2321.15,662.47 2321.15,702.8
  Top Layer w25: C222.2@1344.99,977.27 1344.99,1027.24 1344.99,1234.99 1385,1275 1654.98,1275 v1(1725,1205) v1@1725.14,1205
  Signal Layer 2 w20: 2259.84,3409.36 2259.84,3505.66 2290,3535.82 v1(2290,3630) ; 2294.2,2959.31 2360,2893.51 2360,2670 2299.9,2609.9 2299.9,2499.1 v1(2321.36,2477.64)
  Signal Layer 1 w20: 640,-3100 745,-3100 765,-3080 765,-2845.67 835.67,-2775 1434.45,-2775 1465,-2805.55 1465,-2915 1536.43,-2986.43 2658.57,-2986.43 2695.8,-2949.2 2695.8,-400.8 2685,-390 2636.6,-390
  Signal Layer 4 w25: 5,925 80,925 100,945 J305.12@100,978.35 ; SGND.1@2613.78,2714.34 2675,2775.56
  Signal Layer 4 w39.37: J301.12@100,-1104.33 J301.10@100,-1054.33 J301.8@100,-1004.33 J301.6@100,-954.33 ; J305.12@100,978.35 J305.10@100,1028.35 J305.8@100,1078.35 J305.6@100,1128.35 ; J300.12@804.72,-1104.33 J300.10@804.72,-1054.33 J300.8@804.72,-1004.33 J300.6@804.72,-954.33 ; J304.12@804.72,978.35 J304.10@804.72,1028.35 J304.8@804.72,1078.35 J304.6@804.72,1128.35 ; J302.12@1509.45,-1104.33 J302.10@1509.45,-1054.33 J302.8@1509.45,-1004.33 J302.6@1509.45,-954.33 ; J306.12@1509.45,978.35 J306.10@1509.45,1028.35 J306.8@1509.45,1078.35 J306.6@1509.45,1128.35 ; J303.12@2214.17,-1104.33 J303.10@2214.17,-1054.33 J303.8@2214.17,-1004.33 J303.6@2214.17,-954.33
  Bottom Layer w16: C217.2@1700.27,-2721.5 1752.87,-2721.5 C218.2@1755,-2723.62 1768.98,-2737.6 U202.4@1804.31,-2737.6 U202.3@1829.91,-2737.6 ; C216.2@1829.91,-2793.03 U202.3@1829.91,-2737.6 ; U202.2@1854.88,-2737.6 U202.3@1829.91,-2737.6 ; U202.2@1854.88,-2725 v1(1854.88,-2680) C215.2@1854.88,-2588.56 ; C202.2@2241.5,375 C203.2@2241.5,430 C219.2@2241.5,485 C204.2@2241.5,540 C225.2@2241.5,595.65 R214.1@2241.5,691.5
  Bottom Layer w20: U402.7@1878.5,1072.2 C404.2@1878.5,1198.7 1878.5,1348.5 2097.72,1567.72 U403.7@2207.13,1567.72 ; R221.1@2191.44,2640.6 v1(2211.55,2660.71) ; U405.7@2203.28,3630 U405.7@2214.4,3630 ; U404.7@2207.13,2064.42 2322.92,2064.42 ; U403.7@2223.43,1571.76 C407.1@2223.43,1630.3 ; C410.2@2224.06,3757.29 2224.06,3639.66 U405.7@2214.4,3630 ; C407.1@2225.56,1630.3 C406.2@2225.56,1695.07 2225.56,1697.81 2262.75,1735 2262.75,1988.08 2323.5,2048.83 C408.2@2323.5,2191.71 ; U400.7@2237.72,1075 2265,1075 2305.9,1115.9 C402.2@2305.9,1190.64 ; C209.2@2307.38,2418.58 C209.2@2321.16,2432.36 C209.2@2322.81,2434.01 ; C200.2@2338.5,433.5 R217.1@2338.5,705.72 ; 2362.5,3480 U405.11@2417.84,3480 ; U405.13@2417.84,3380 2375,3380 2360,3395 2360,3560 v1(2290,3630) U405.7@2214.4,3630 ; C314.2@2546.22,-2537.98 2560,-2551.76 U300.2@2560,-2629.64
  Bottom Layer w25: C211.2@2191.44,2518.01 2191.44,2445.11 2217.97,2418.58 v1(2276.51,2418.58) C209.2@2307.38,2418.58 ; C209.2@2321.16,2432.36 2321.16,2406.24 2388.1,2339.3 2388.1,2257.58 2323.5,2192.98 C408.2@2323.5,2191.71
  Bottom Layer w39.37: C209.2@2322.81,2434.01 U200.4@2322.81,2524.52
  Bottom Layer w50: C208.2@2394.42,2731.3 2503.49,2731.3 C207.2@2507.15,2727.64 2520.45,2714.34 SGND.1@2613.78,2714.34
  other v1: 2560,-2585.61 2495,-2470 2315,-1100 2315,-1054.33 2315,-1010 2315,-965 2605,-385 1734.8,-188.31 1770,-188.31 1905,-188.31 1734.8,-155 1770,-155 1905,-155 1735,-120 1770,-120 1905,-120 1735,-85 1771.15,-85 1906.15,-85 1734.8,-50 1771.15,-50 1906.15,-50 2290,390 2290,500.43 2290,610 2290,715 1965,805 2289.17,809.03 2654.88,827.73 2320.77,912.9 1948.5,915 2655,937.73 1948.5,1027.5 2654.98,1047.73 1831.87,1072.2 1831.87,1133.99 2655,1157.2 1831.87,1199.42 2653.84,1265 1945.55,1330 2630,1376.46 1755,1499.51 1980,1580 2130.67,1610.1 1980,1615 2011.5,1615 2130.67,1665 1638.58,1670 1676.81,1670 1638.58,1710 2317.21,1960 2291.23,2110 2302.97,2155 2454.7,2285 2653.43,2285 2653.43,2420 2276.71,2447.49 2478.72,2452.46 2276.51,2477.64 2287.91,3395 2588.57,3455 1948.5,3494.26 2588.57,3630 2135,3705 2135,3755 2565.57,3885 2530,3920 1625,3926.22 2675,3926.22 2645,3975
  other v2: 100,-3475 140,-3475 180,-3475 220,-3475 260,-3475 300,-3475 350,-3475 390,-3475 430,-3475 470,-3475 510,-3475 550,-3475 100,-3435 140,-3435 180,-3435 220,-3435 260,-3435 300,-3435 350,-3435 390,-3435 430,-3435 470,-3435 510,-3435 550,-3435 100,-3395 140,-3395 180,-3395 220,-3395 260,-3395 300,-3395 350,-3395 390,-3395 430,-3395 470,-3395 510,-3395 550,-3395 100,-3355 140,-3355 180,-3355 220,-3355 260,-3355 300,-3355 350,-3355 390,-3355 430,-3355 470,-3355 510,-3355 550,-3355 95,-2920 555,-2920 95,-2880 555,-2880 95,-2840 135,-2840 175,-2840 475,-2840 515,-2840 555,-2840
  other v4: 2500.64,210 2128.54,240.3
SOH_L: J200.103 | length 120.6
  Top Layer w20: J200.103@2377.73,1847.93 2498.31,1847.93
SYNC_START_L: J200.93 | length 106.8
  Top Layer w20: J200.93@2377.73,1690.45 2484.54,1690.45
SYNC_STOP_L: J200.95 | length 108.8
  Top Layer w20: J200.95@2377.73,1721.95 2486.5,1721.95
Temp_sensor: J200.81
Total_charge_current_battery: C225.1 J200.34 R231.2 | length 292.4
  Top Layer w20: R231.2@1936.5,650 2094.59,650 2125.01,619.58 v1(2130,619.58) 2157.93,619.58
  Bottom Layer w20: v1(2130,619.58) 2139.58,610 2164.16,610 C225.1@2178.5,595.65
Total_discharge_current_bus: C219.1 J200.28 R227.2 | length 409.8
  Top Layer w20: R227.2@1936.5,540 v1(2105,540) 2119.9,525.1 J200.28@2243.87,525.1
  Bottom Layer w20: v1(2105,540) 2119.9,525.1 2132.68,525.1 2172.77,485 C219.1@2178.5,485
UART_RX_A_SFRA: J200.76
UART_TX_A_SFRA: J200.78
V_battery: J200.40 R208.1 R214.2 | length 389.9
  Top Layer w20: R208.1@1937.81,760.67 1947.51,760.67 1994.11,714.07 J200.40@2243.87,714.07
  Bottom Layer w20: v1(2120,715) 2171.29,715 R214.2@2180.64,705.65
V_battery1: J200.36 R209.1 R215.2 | length 380.5
  Top Layer w20: R209.1@1936.5,705 1966.7,705 1983.42,688.27 2092.81,688.27 v1(2130,651.08) J200.36@2243.87,651.08
  Bottom Layer w20: v1(2130,651.08) 2180.21,651.08 R215.2@2180.64,650.65
VBAT-: C300.2 C301.2 C302.2 C303.2 C304.2 C305.2 C306.2 C307.2 C308.2 T302.1 TP302.1 TP305.1 TP308.1 TP311.1 TP319.1 TP320.1 TP326.1 TP329.1 TP332.1 TP338.1 TP341.1 TP344.1 TP347.1 TP355.1
  other v1: 1490,1502.46 1325,1503.3 1410,1503.3 975,1505 1065,1505 1156.46,1505 1241.1,1505 1490,1577.46 1325,1578.3 1410,1578.3 975,1580 1065,1580 1156.46,1580 1241.1,1580
  other v2: 931.42,3277.87 971.42,3277.87 1011.42,3277.87 1311.42,3277.87 1351.42,3277.87 1391.42,3277.87 931.42,3317.87 1391.42,3317.87 931.42,3357.87 1391.42,3357.87 936.42,3792.87 976.42,3792.87 1016.42,3792.87 1056.42,3792.87 1096.42,3792.87 1136.42,3792.87 1186.42,3792.87 1226.42,3792.87 1266.42,3792.87 1306.42,3792.87 1346.42,3792.87 1386.42,3792.87 936.42,3832.87 976.42,3832.87 1016.42,3832.87 1056.42,3832.87 1096.42,3832.87 1136.42,3832.87 1186.42,3832.87 1226.42,3832.87 1266.42,3832.87 1306.42,3832.87 1346.42,3832.87 1386.42,3832.87 936.42,3872.87 976.42,3872.87 1016.42,3872.87 1056.42,3872.87 1096.42,3872.87 1136.42,3872.87 1186.42,3872.87 1226.42,3872.87 1266.42,3872.87 1306.42,3872.87 1346.42,3872.87 1386.42,3872.87 936.42,3912.87 976.42,3912.87 1016.42,3912.87 1056.42,3912.87 1096.42,3912.87 1136.42,3912.87 1186.42,3912.87 1226.42,3912.87 1266.42,3912.87 1306.42,3912.87 1346.42,3912.87 1386.42,3912.87
VOUT_SEL: J200.90
pads on no net: J200.1 J200.2 J200.3 J200.4 J200.5 J200.6 J200.8 J200.9 J200.11 J200.12 J200.13 J200.14 J200.16 J200.17 J200.20 J200.23 J200.27 J200.29 J200.32 J200.33 J200.41 J200.43 J200.44 J200.66 J200.71 J200.73 J200.86 J200.92 J200.94 J200.96 J200.113 J200.114 J200.115 J200.116 J200.117 J200.118 J200.119 J200.181 J200.182 J200.185 J200.186 J201.2 J201.4 J202.61 J202.62 J202.121 J202.122 J202.123 J202.124 J202.125 J202.126 J202.127 J202.128 J202.129 J202.130 J202.131 J202.132 J202.133 J202.134 J202.136 J202.137 J202.138 J202.139 J202.140 J202.141 J202.142 J202.143 J202.144 J202.145 J202.146 J202.147 J202.148 J202.149 J202.150 J202.151 J202.152 J202.153 J202.154 J202.155 J202.162 J202.163 J202.164 J202.165 J202.166 J202.167 J202.168 J202.169 J202.170 J202.171 J202.172 J202.173 J202.174 J202.175 J202.176 J202.177 J202.178 J300.7 J301.7 J302.7 J303.7 J304.7 J305.7 J306.7 U200.2 U200.5 U201.4 U405.10 U405.12
copper on no net:
  other v3: 2379.53,2600.56 2399.21,2600.56 2418.9,2600.56 2379.53,2639.93 2399.21,2639.93 2418.9,2639.93

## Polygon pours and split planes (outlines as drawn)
48VOUT1 on Bottom Layer "48Vout1" (solid, remove dead copper, pour order 272): 1565,-2670.99 1540.35,-2646.35 1540.35,-2427.64 1562.99,-2405 2313.43,-2405 2348.43,-2440 2348.43,-2638.79 2317.21,-2670 2120,-2670 2001.76,-2551.76 1810.99,-2551.76 1691.75,-2670.99
SGND on Bottom Layer "SGND" (solid, remove dead copper, pour order 201): 935.71,-1990 935.71,-2299.2 820,-2414.91 820,-3503.58 800.67,-3522.92 12.92,-3522.92 -18.98,-3491.02 -18.98,-1990
VBAT- on Bottom Layer "VBAT-" (solid, remove dead copper, pour order 200): 865.47,3995 820.47,3950 820.47,3275 845.47,3250 1535.47,3250 1580.47,3295 1580.47,3950 1535.47,3995
CS-_total_charge_current_battery on Bottom Layer "CS-_total_charge_current_battery" (solid, remove dead copper, pour order 195): 2240,-1143.28 2343.23,-1246.51 2343.23,-1518.28 2306.51,-1555 15,-1555 -20,-1520 -20,3960 15,3995 700,3995 765,3930 765,3244.99 814.99,3195 1410,3195 1580,3025 1580,1416.16 1421.49,1257.65 1421.49,757.43 1395,730.94 1310.94,730.94 1275,695 1275,640 1310,605 1395,605 1421.49,578.51 1421.49,-191.22 1516.54,-286.27 1516.54,-566.54 1560,-610 1775.27,-610 2092.28,-927.02 2092.28,-1119.55 2116.07,-1143.33
5V on Bottom Layer "5V" (solid, remove dead copper, pour order 176): 2443.65,2558.35 2462.77,2577.46 2518.93,2577.46 2533.44,2562.95 2533.44,2497.36 2513.72,2477.64 2467.46,2477.64 2453.68,2463.86 2453.68,2391.02 2447.77,2385.12 2374.94,2385.12 2369.03,2391.02 2369.03,2463.86 2369.03,2554.41 2372.97,2558.35
48VOUT2 on Bottom Layer "48Vout2" (solid, remove dead copper, pour order 151): 890,-2820 850,-2860 850,-3488.58 901.42,-3540 2660,-3540 2715,-3485 2715,-3045 2685,-3015 1440,-3015 1411.42,-2986.42 1411.42,-2833.68 1397.73,-2820
5V on Bottom Layer "5V" (solid, remove dead copper, pour order 144): 2361.16,2558.35 2355.25,2552.44 2355.25,2477.64 2369.03,2463.86 2369.03,2391.02 2374.94,2385.12 2447.77,2385.12 2453.68,2391.02 2453.68,2546.54 2441.87,2558.35
CS+_total_charge_current_battery on Bottom Layer "CS+_total_charge_current_battery" (solid, remove dead copper, pour order 208): 1450,785 1480,815 1668.05,815 1699.53,783.52 1699.53,539.53 1670,510 1455,510 1450,515
SGND on Bottom Layer "SGND" (solid, remove dead copper, pour order 210): 1699.99,110 1450,110 1450,-135 1500,-185 1644.6,-185 1699.8,-129.8
CS-_total_discharge_current_bus on Bottom Layer "CS-_total_discharge_current_bus" (solid, remove dead copper, pour order 212): 2560,-2750 2560,-2761.9 2573.1,-2775 2674.26,-2775 2700,-2800.74 2700,-2901.14 2661.14,-2940 1520,-2940 1487.2,-2907.2 1487.2,-2782.8 1520,-2750 1900,-2750 1910,-2760 1910,-2785 1920,-2795 1960,-2795 1985.1,-2769.9 2030.16,-2769.9 2050,-2750.06 2050,-2750
SGND on Bottom Layer "SGND" (solid, remove dead copper, pour order 242): 2700,3950 2655,3995 1635,3995 1590,3950 1590,925 1710,805 1710,-185 1735,-210 2405,-210 2610,-415 2675,-415 2700,-390
48VOUT2 on Bottom Layer "48V2" (solid, remove dead copper, pour order 226): 2360,-1525 2310,-1575 1175.01,-1575 950,-1799.98 950,-2655 850,-2755 850,-2860 1385,-2860 1525,-2720 1525,-2430 1555,-2400 2605,-2400 2705,-2300 2705,-525 2400,-220 1566.54,-220 1525,-261.54 1525,-566.18 1558.82,-600 1784.02,-600 1984.02,-800 2240,-800 2360,-920
SGND on Bottom Layer "SGND" (solid, remove dead copper, pour order 304): 1820,-2804.42 1766.76,-2751.18 1686.18,-2751.18 1675,-2740 1675,-2702.09 1682.09,-2695 1770,-2695 1780,-2685 1820.99,-2685 1835,-2670.99 1835,-2570 1840,-2565 1865,-2565 1870,-2570 1870,-2784.69 1850.27,-2804.42
SGND on Bottom Layer "SGND" (solid, remove dead copper, pour order 308): 2485,-2452.48 2475,-2462.48 2475,-2545 2537.4,-2607.4 2537.4,-2663.88 2553.04,-2679.51 2565.49,-2679.51 2580,-2665 2580,-2463.58 2568.9,-2452.48
VBAT- on Bottom Layer "VBAT-" (solid, remove dead copper, pour order 310): 1670,120 1450,120 1450,427.34 1459.45,436.79 1608.21,436.79 1670,375
VBAT- on Top Layer "VBAT-" (solid, remove dead copper, pour order 280): 15,-1630 2333.59,-1630 2380,-1676.41 2380,-1975 -18.98,-1975 -18.98,-1663.98
SGND on Top Layer "VBAT-" (solid, remove dead copper, pour order 244): 14.61,-2715 -18.98,-2748.59 -18.98,-3491.41 14.61,-3525 665,-3525 700,-3490 700,-2750 665,-2715
48VOUT2 on Top Layer "48Vout2" (solid, remove dead copper, pour order 148): 895,-2820 850,-2865 850,-3488.58 901.42,-3540 2660,-3540 2715,-3485 2715,-3030 2670,-2985 1455,-2985 1435,-2965 1435,-2860 1395,-2820
VBAT- on Top Layer "SGND" (solid, remove dead copper, pour order 206): 1580.71,1467.72 1580.71,1466.26 1555,1440 975,1440 972.72,1440 945,1467.72 945,1978.96 765,2158.96 765,3950 810.36,3995.36 1534.64,3995.36 1580.71,3949.29 1580.71,2135
CS-_total_charge_current_battery on Top Layer "CS-_total_charge_current_battery" (solid, remove dead copper, pour order 146): 750,3950 700,4000 30,4000 -30,3940 -30,2225 -30,555.1 0,525.1 905.34,525.1 936.42,556.17 936.42,1970.91 748.66,2158.66 750,2160
5V on Top Layer "5V" (solid, remove dead copper, pour order 145): 2441.87,2558.35 2453.52,2570 2520,2570 2535,2555 2535,2495 2520,2480 2481.22,2480 2453.68,2452.46 2453.68,2391.02 2447.77,2385.12 2374.94,2385.12 2369.03,2391.02 2369.03,2463.86 2369.03,2554.41 2372.97,2558.35
CS-_total_discharge_current_bus on Top Layer "CS-_total_discharge_current_bus" (solid, remove dead copper, pour order 154): 1900,-2750 1910,-2760 1910,-2785 1920,-2795 1960,-2795 1970,-2785 1970,-2760 1980,-2750 2650.64,-2750 2700,-2799.36 2700,-2910 2670,-2940 1520,-2940 1487.2,-2907.2 1487.2,-2782.8 1520,-2750
CS+_total_charge_current_battery on Top Layer "CS+_total_charge_current_battery" (solid, remove dead copper, pour order 222): 1104.58,619.58 1056.42,571.42 1056.42,408.39 1064.44,400.37 1544.9,400.37 1549.53,405 1640,405 1670,435 1670,815 1645,840 1513.96,840 1445,771.04 1445,655 1409.58,619.58
SGND on Top Layer "SGND" (solid, remove dead copper, pour order 224): 1670,-50 1745,-50 1745,-220 -5,-220 -18.98,-206.02 -18.98,110 1670,110
48VOUT2 on Top Layer "48Vout2" (solid, remove dead copper, pour order 228): 1330.25,-265 1315.25,-280 1315,-280 1315,-495 1405,-585 1625.74,-585 1645.74,-565 1645.74,-293.81 1616.93,-265
48VOUT1 on Top Layer "48Vout1" (solid, remove dead copper, pour order 230): 125,-265 105,-285 105,-575 125,-595 930,-595 950,-575 950,-285 930,-265
CS-_total_charge_current_battery on Top Layer "CS-" (solid, remove dead copper, pour order 232): 20,-1180 -20,-1220 -20,-1575 20,-1615 2338.59,-1615 2378.59,-1575 2378.59,-1223.59 2335,-1180
SGND on Top Layer "SGND" (solid, remove dead copper, pour order 234): -18.98,-1975 2380,-1975 2380,-2258.59 2343.59,-2295 15,-2295 -18.98,-2261.02
48VOUT1 on Top Layer "48Vout1" (solid, remove dead copper, pour order 236): 1830,-2700 1838.48,-2691.52 1838.66,-2667.5 1846.55,-2659.61 1885.39,-2659.61 1925,-2620 1925,-2590.61 1929.31,-2586.3 1950.69,-2586.3 1955,-2590.61 1955,-2689.61 1965,-2700 2395,-2700 2435,-2660 2435,-2345.79 2399.21,-2310 15,-2310 -18.98,-2343.98 -18.98,-2666.02 15,-2700
SGND on Top Layer "SGND" (solid, remove dead copper, pour order 238): 1335.25,1395 1545.74,1395 1645.74,1295 1680,1295 1710,1325 1710,1531.93 1590,1651.93 1590,3950 1635,3995 2655,3995 2700,3950 2700,-2700 2665,-2735 2518.88,-2735 2445,-2661.12 2445,-2335 2390,-2280 2390,-1220 2340,-1170 20,-1170 20,-615 1615,-615 1710,-520 1710,827.54 1660.74,876.81 1491.41,876.81 1429.61,815 1346.74,815 1286.74,875 1151.81,875 1102.43,875 1061.1,916.33 1061.1,1120.85
VBAT- on Top Layer "VBAT-" (solid, remove dead copper, pour order 282): -18.98,120 -18.98,496.02 0,515 924.4,515 1040.29,399.11 1645.9,399.11 1670,375.01 1670,120
5V on Signal Layer 1 "5V" (solid, remove dead copper, pour order 141): 2433.44,2558.35 2450.04,2574.95 2512.66,2574.95 2533.54,2554.08 2533.54,2494.15 2520.23,2480.85 2369.03,2480.85 2369.03,2554.41 2372.97,2558.35
CS-_total_charge_current_battery on Signal Layer 1 "CS-_total_charge_current_battery" (solid, remove dead copper, pour order 171): 10,3245 -20,3275 -20,3950 25,3995 541.77,3995 586.77,3950 586.77,3266.77 565,3245
SGND on Signal Layer 1 "SGND" (solid, remove dead copper, pour order 169): 2405,-2290 2345,-2350 1925,-2350 1825,-2450 1825,-2684.61 1865.39,-2725 2624.61,-2725 2670.4,-2679.21 2670.4,-1130.22 2670,-1129.82 2670,3965 2640,3995 1635,3995 1590,3950 1590,3938.81 1590.22,1650.22 1710,1530.43 1710,-1044.12 1805.7,-1139.82 2365,-1139.82 2405,-1179.82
